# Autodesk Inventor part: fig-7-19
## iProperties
Created: 2004-05
Part Number: fig-7-19
Document SubType Name: Modeling
Designer: CADCIM Technologies
Manufacturer: Standard
Standards Organization: Custom
Density: 1 g/cm^3
Author: CADCIM Technologies
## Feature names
1. Extrusion1
2. Loft2
